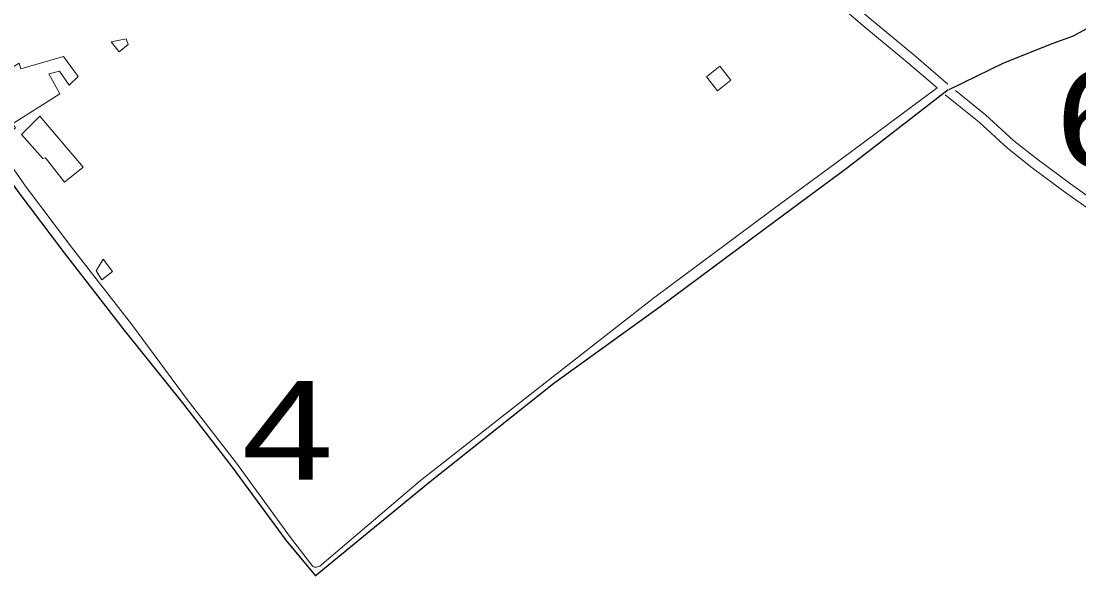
# Model space of a CAD drawing. Extents: x 476989 to 498418, y 4381813 to 4416555.
# Drawn here: x 486244 to 486780, y 4385659 to 4385941 of the extents above; entities that cross this region are included whole.
import ezdxf
from ezdxf.enums import TextEntityAlignment as Align

# ---------------------------------------------------------------- set-up
doc = ezdxf.new("R2010")
doc.units = 0
doc.header["$LTSCALE"] = 20
for name, color, linetype, lineweight in [('13', 7, 'Continuous', 13), ('36', 7, 'Continuous', 13), ('47', 7, 'Continuous', 13), ('6', 7, 'Continuous', 25)]:
    doc.layers.add(name, color=color, linetype=linetype, lineweight=lineweight)

msp = doc.modelspace()

# ---------------------------------------------------------------- linework, layer by layer
at = {"layer": '36'}
for points in [[(486544.6, 4386061.6), (486555.49, 4386051.99), (486565.36, 4386044.57), (486575.71, 4386035.06), (486585.66, 4386026.27), (486595.98, 4386018.4), (486606.16, 4386009.36), (486610.66, 4386004.2), (486616.49, 4385997.98), (486623.5, 4385989.46), (486633.36, 4385979.55), (486643.2, 4385970.03), (486651.2, 4385962.02), (486657.07, 4385957.05), (486674.26, 4385942.1), (486696.74, 4385923.39), (486714.13, 4385908.6)], [(486653.82, 4385953.26), (486671.02, 4385938.29), (486693.52, 4385919.56), (486708.56, 4385906.77)], [(486142.37, 4385922.73), (486169.25, 4385920.92), (486183.49, 4385918.24), (486188.02, 4385917.05), (486195.24, 4385913.48), (486204.23, 4385908.31), (486209.48, 4385904.02), (486213.82, 4385898.89), (486218.57, 4385893.02), (486230.28, 4385879.98), (486246.4, 4385856.86), (486269.75, 4385825.93), (486300.13, 4385786.91), (486328.91, 4385748), (486353.38, 4385716.35), (486380.75, 4385678.67), (486392.21, 4385664.02)], [(486395.73, 4385664.21), (486446.64, 4385707.54), (486509.86, 4385757.05), (486564.88, 4385800.1), (486623.66, 4385843.75), (486659.91, 4385870.62), (486708.56, 4385906.77)], [(486712.77, 4385903.18), (486729.88, 4385889.29), (486744.34, 4385876.09), (486756.73, 4385866.21), (486773.27, 4385853.94), (486788.78, 4385843.03)], [(486717.93, 4385905.42), (486733.14, 4385893.08), (486747.58, 4385879.89), (486759.77, 4385870.17), (486776.19, 4385857.99), (486791.65, 4385847.12)], [(486392.21, 4385664.02), (486392.47, 4385663.82), (486392.98, 4385663.7), (486393.43, 4385663.66), (486393.99, 4385663.64), (486394.55, 4385663.73), (486395.2, 4385663.92), (486395.73, 4385664.21)]]:
    msp.add_lwpolyline(points, dxfattribs=at)
at = {"layer": '47'}
for points in [[(486289.92, 4385930.05), (486297.45, 4385931.59), (486298.53, 4385928.65), (486293.97, 4385924.89)], [(486265.73, 4385922.59), (486251.79, 4385918.59), (486244.03, 4385916.37), (486243.24, 4385919.16), (486232.42, 4385912.64), (486224.03, 4385908.18), (486225.24, 4385903.96), (486224.11, 4385903.38), (486225.41, 4385900.28), (486230.23, 4385901.41), (486231.25, 4385898.92), (486235.75, 4385893.61), (486231.72, 4385890.14), (486236.49, 4385882.79), (486241.42, 4385886.4), (486239.95, 4385888.52), (486263.96, 4385903.63), (486258.32, 4385913.84), (486263.67, 4385915.19), (486268.6, 4385908.14), (486273.16, 4385912.43)], [(486604.04, 4385910.54), (486597.3, 4385905.2), (486591.69, 4385912.29), (486598.43, 4385917.63)], [(486275.73, 4385866.54), (486253.81, 4385892.3), (486244.45, 4385883.13), (486255.23, 4385870.81), (486256.66, 4385871.24), (486266.32, 4385858.95)], [(486290.5, 4385813.58), (486285.12, 4385809.31), (486282.25, 4385813.92), (486285.87, 4385819.8)]]:
    msp.add_lwpolyline(points, close=True, dxfattribs=at)
at = {"layer": '6'}
for points in [[(486714.69, 4385905.9), (486742.52, 4385919.31), (486767.38, 4385929.3), (486777.82, 4385933.01), (486790.63, 4385940.11)], [(486142.05, 4385918.05), (486168.65, 4385916.25), (486182.46, 4385913.66), (486186.37, 4385912.63), (486193.03, 4385909.34), (486201.55, 4385904.44), (486206.17, 4385900.66), (486210.21, 4385895.9), (486215, 4385889.97), (486226.59, 4385877.06), (486242.6, 4385854.11), (486266.03, 4385823.08), (486296.39, 4385784.07), (486326.62, 4385746.3), (486351.18, 4385714.3), (486378.4, 4385677.31), (486393.42, 4385659.22)], [(486393.35, 4385659.22), (486450.78, 4385706.33), (486514.27, 4385756.91), (486568.15, 4385795.81), (486626.88, 4385839.42), (486663.13, 4385866.29), (486714.2, 4385905.9)]]:
    msp.add_lwpolyline(points, dxfattribs=at)

# ---------------------------------------------------------------- texts
at = {"layer": '13', "width": 1.25}
for s, p in [('6', (486791.76, 4385865.93)), ('4', (486379.3, 4385707.97))]:
    msp.add_text(s, height=50, dxfattribs=at).set_placement(p, align=Align.CENTER)

doc.saveas('drawing.dxf')
